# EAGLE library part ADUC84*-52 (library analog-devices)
ADuC845/ADuC847/ADuC848 Package MQFP 52 Source: http://www.analog.com/static/imported-files/data_sheets/ADUC845_847_848.pdf
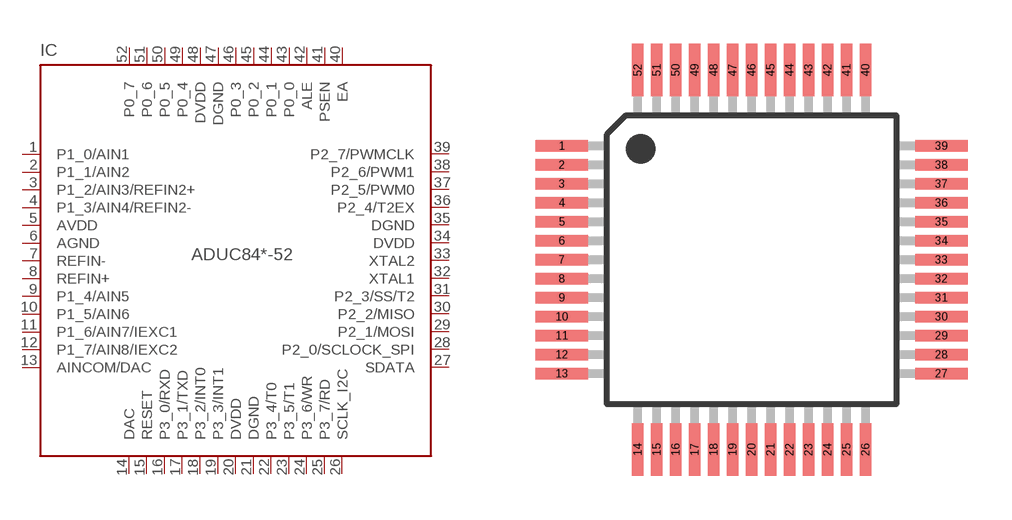
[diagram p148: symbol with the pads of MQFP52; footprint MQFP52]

Designator prefix IC

## ADUC845-52 (MPN: ADUC845BSZ62-5; OC_FARNELL: 1438809; OC_NEWARK: 15P0574), ADUC847-52 (MPN: ADUC847BSZ62-3; OC_FARNELL: 1438810; OC_NEWARK: 15P0575), ADUC848-52 (MPN: ADUC848BSZ62-5; OC_FARNELL: 1438811; OC_NEWARK: 15P0578)  [MQFP52]
1  P1_0/AIN1  in
2  P1_1/AIN2  in
3  P1_2/AIN3/REFIN2+  in
4  P1_3/AIN4/REFIN2-  in
5  AVDD  pwr
6  AGND  pwr
7  REFIN-  in
8  REFIN+  in
9  P1_4/AIN5  in
10  P1_5/AIN6  in
11  P1_6/AIN7/IEXC1
12  P1_7/AIN8/IEXC2
13  AINCOM/DAC
14  DAC  out
15  RESET  in
16  P3_0/RXD
17  P3_1/TXD
18  P3_2/INT0
19  P3_3/INT1
20  DVDD  pwr
21  DGND  pwr
22  P3_4/T0
23  P3_5/T1
24  P3_6/WR
25  P3_7/RD
26  SCLK_I2C
27  SDATA
28  P2_0/SCLOCK_SPI
29  P2_1/MOSI
30  P2_2/MISO
31  P2_3/SS/T2
32  XTAL1  in
33  XTAL2  out
34  DVDD  pwr
35  DGND  pwr
36  P2_4/T2EX
37  P2_5/PWM0
38  P2_6/PWM1
39  P2_7/PWMCLK
40  EA  in
41  PSEN  out
42  ALE  out
43  P0_0
44  P0_1
45  P0_2
46  P0_3
47  DGND  pwr
48  DVDD  pwr
49  P0_4
50  P0_5
51  P0_6
52  P0_7

## Footprint MQFP52 (pad centres in mm)
52-Lead Metric Quad Flat Package MQFP S-52-2 COMPLIANT TO JEDEC STANDARDS MO-112-AC-1 Source: http://www.analog.com/static/imported-files/data_sheets/ADUC845_847_848.pdf
smd 1.8 x 0.4: 1 -6.5,3.9; 2 -6.5,3.25; 3 -6.5,2.6; 4 -6.5,1.95; 5 -6.5,1.3; 6 -6.5,0.65; 7 -6.5,0; 8 -6.5,-0.65; 9 -6.5,-1.3; 10 -6.5,-1.95; 11 -6.5,-2.6; 12 -6.5,-3.25; 13 -6.5,-3.9; 27 6.5,-3.9; 28 6.5,-3.25; 29 6.5,-2.6; 30 6.5,-1.95; 31 6.5,-1.3; 32 6.5,-0.65; 33 6.5,0; 34 6.5,0.65; 35 6.5,1.3; 36 6.5,1.95; 37 6.5,2.6; 38 6.5,3.25; 39 6.5,3.9
smd 0.4 x 1.8: 14 -3.9,-6.5; 15 -3.25,-6.5; 16 -2.6,-6.5; 17 -1.95,-6.5; 18 -1.3,-6.5; 19 -0.65,-6.5; 20 0,-6.5; 21 0.65,-6.5; 22 1.3,-6.5; 23 1.95,-6.5; 24 2.6,-6.5; 25 3.25,-6.5; 26 3.9,-6.5; 40 3.9,6.5; 41 3.25,6.5; 42 2.6,6.5; 43 1.95,6.5; 44 1.3,6.5; 45 0.65,6.5; 46 0,6.5; 47 -0.65,6.5; 48 -1.3,6.5; 49 -1.95,6.5; 50 -2.6,6.5; 51 -3.25,6.5; 52 -3.9,6.5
